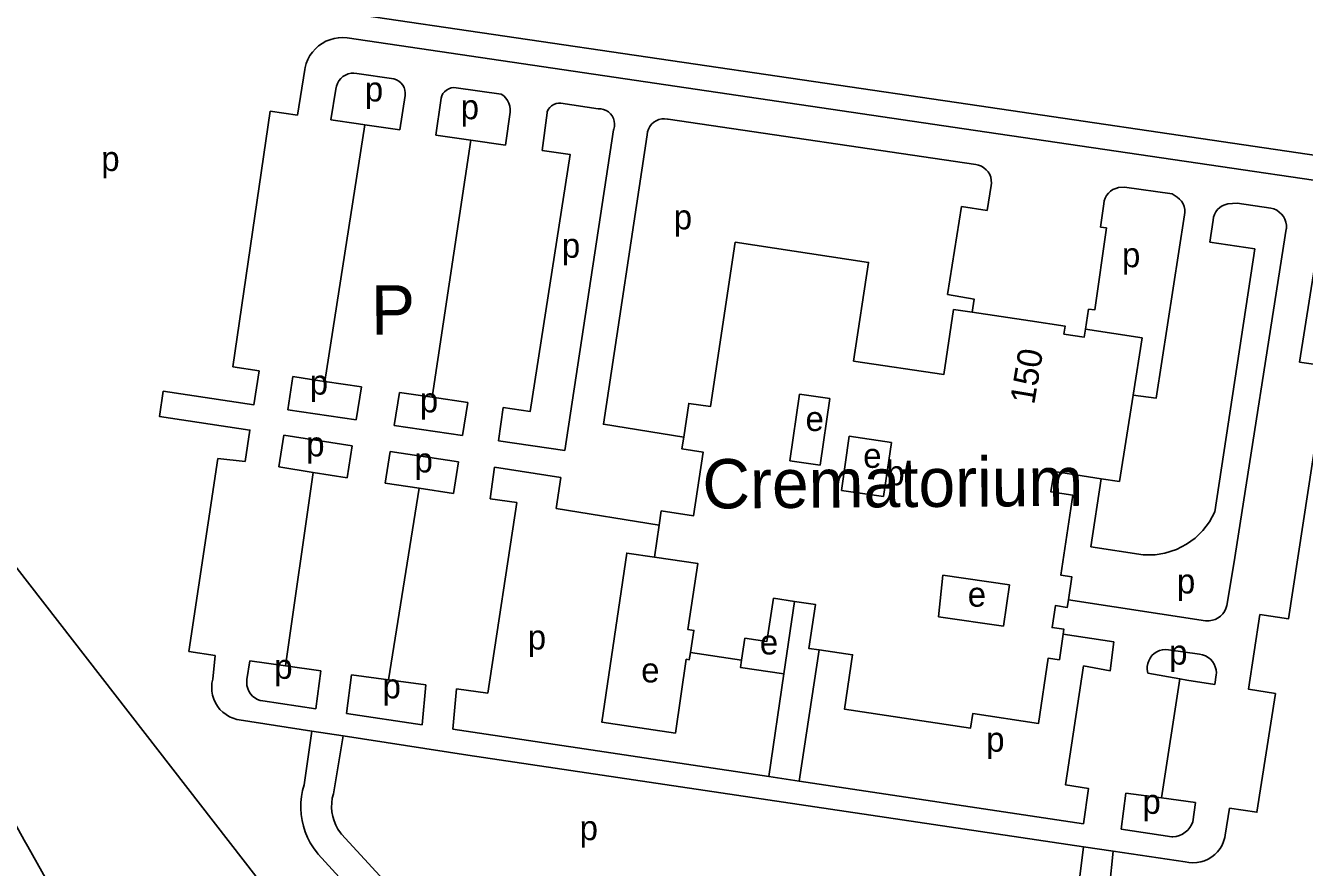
# Model space of a CAD drawing. Extents: x 156097 to 158136, y 385644 to 388348.
# Drawn here: x 156481.1 to 156688.7, y 385843.2 to 385979.8 of the extents above; entities that cross this region are included whole.
import ezdxf

# ---------------------------------------------------------------- set-up
doc = ezdxf.new("R2010")
doc.units = 0
for name, color, linetype in [('BLT_Basislijn', 7, 'Continuous'), ('BLT_Bebouwing', 7, 'Continuous'), ('BLT_Bebouwing_beschrifting', 7, 'Continuous'), ('BLT_Centroide', 7, 'Continuous'), ('BLT_Huisnummer', 7, 'Continuous')]:
    doc.layers.add(name, color=color, linetype=linetype)

msp = doc.modelspace()

# ---------------------------------------------------------------- linework, layer by layer
at = {"layer": 'BLT_Basislijn'}
for p, q in [((156526.39, 385972.7), (156525.24, 385965.31)), ((156534.87, 385972.08), (156540.88, 385971.22)), ((156531.46, 385969.52), (156530.63, 385964.53)), ((156550.97, 385969.74), (156558.3, 385968.71)), ((156542.7, 385968.51), (156541.83, 385962.92)), ((156548.51, 385967.67), (156547.65, 385962.08)), ((156567.99, 385967.23), (156574.03, 385966.35)), ((156520.79, 385965.95), (156514.73, 385924.48)), ((156520.79, 385965.95), (156525.24, 385965.31)), ((156530.63, 385964.53), (156535.15, 385963.89)), ((156559.74, 385965.8), (156559.01, 385960.45)), ((156565.73, 385965.7), (156564.96, 385959.59)), ((156585.38, 385964.65), (156635.31, 385957.31)), ((156536.14, 385963.74), (156529.68, 385922.09)), ((156535.15, 385963.89), (156536.14, 385963.74)), ((156536.14, 385963.74), (156541.83, 385962.92)), ((156576.51, 385962.92), (156568.64, 385910.87)), ((156553.34, 385961.26), (156547.07, 385919.53)), ((156547.65, 385962.08), (156553.34, 385961.26)), ((156553.34, 385961.26), (156559.01, 385960.45)), ((156637.83, 385953.89), (156637.15, 385949.85)), ((156659.48, 385953.63), (156667.2, 385952.52)), ((156637.15, 385949.85), (156633.02, 385950.46)), ((156656.12, 385950.92), (156655.58, 385947.14)), ((156683.24, 385950.23), (156677.73, 385951.02)), ((156656.54, 385947), (156655.58, 385947.14)), ((156685.73, 385946.79), (156677.19, 385892.5)), ((156653.11, 385930.57), (156653.63, 385933.85)), ((156519.02, 385923.79), (156514.73, 385924.48)), ((156524.47, 385922.91), (156523.64, 385917.49)), ((156528.84, 385922.21), (156524.47, 385922.91)), ((156529.68, 385922.09), (156528.84, 385922.21)), ((156535.59, 385921.22), (156529.68, 385922.09)), ((156535.59, 385921.22), (156534.76, 385915.85)), ((156541.76, 385920.31), (156540.91, 385914.95)), ((156547.07, 385919.53), (156541.76, 385920.31)), ((156552.87, 385918.68), (156547.07, 385919.53)), ((156523.64, 385917.49), (156534.76, 385915.85)), ((156552.87, 385918.68), (156552.01, 385913.32)), ((156558.6, 385917.84), (156557.83, 385912.46)), ((156540.91, 385914.95), (156552.01, 385913.32)), ((156523, 385913.36), (156522.21, 385908.21)), ((156523, 385913.36), (156534.11, 385911.67)), ((156534.11, 385911.67), (156533.3, 385906.46)), ((156540.25, 385910.74), (156539.44, 385905.56)), ((156540.25, 385910.74), (156551.33, 385909.06)), ((156557.83, 385912.46), (156568.64, 385910.87)), ((156512.28, 385909.57), (156507.6, 385878.24)), ((156512.28, 385909.57), (156516.71, 385909.08)), ((156551.33, 385909.06), (156550.52, 385903.93)), ((156522.21, 385908.21), (156527.76, 385907.34)), ((156523.26, 385875.96), (156527.76, 385907.34)), ((156527.76, 385907.34), (156533.3, 385906.46)), ((156557.21, 385908.16), (156556.49, 385903.06)), ((156557.21, 385908.16), (156567.98, 385906.53)), ((156539.44, 385905.56), (156544.98, 385904.75)), ((156544.98, 385904.75), (156540.02, 385873.67)), ((156544.98, 385904.75), (156550.52, 385903.93)), ((156677.19, 385892.5), (156676.07, 385885.71)), ((156605.91, 385886.39), (156604.18, 385874.63)), ((156672.61, 385883.26), (156650.35, 385886.64)), ((156657.74, 385879.86), (156649.52, 385881.08)), ((156507.6, 385878.24), (156511.84, 385877.61)), ((156511.46, 385873.75), (156511.84, 385877.61)), ((156609.9, 385878.55), (156606.68, 385857.22)), ((156671.65, 385877.81), (156666.61, 385878.55)), ((156517.02, 385873.7), (156517.48, 385876.77)), ((156523.26, 385875.96), (156517.48, 385876.77)), ((156529.03, 385875.15), (156523.26, 385875.96)), ((156528.2, 385868.97), (156529.03, 385875.15)), ((156533.15, 385868.23), (156533.99, 385874.48)), ((156540.02, 385873.67), (156533.99, 385874.48)), ((156546.05, 385872.86), (156540.02, 385873.67)), ((156604.18, 385874.63), (156601.73, 385857.96)), ((156663.25, 385874.75), (156668.47, 385873.82)), ((156668.47, 385873.82), (156665.46, 385854.51)), ((156668.47, 385873.82), (156669.61, 385873.62)), ((156669.61, 385873.62), (156674.15, 385872.91)), ((156674.37, 385874.49), (156674.15, 385872.91)), ((156545.46, 385866.39), (156546.05, 385872.86)), ((156550.41, 385865.65), (156551.01, 385872.19)), ((156556.13, 385871.51), (156551.01, 385872.19)), ((156519.57, 385870.26), (156528.2, 385868.97)), ((156515.73, 385867.18), (156527.57, 385865.35)), ((156533.15, 385868.23), (156545.46, 385866.39)), ((156526.28, 385856.64), (156527.57, 385865.35)), ((156527.57, 385865.35), (156532.62, 385864.57)), ((156550.41, 385865.65), (156601.73, 385857.96)), ((156531.05, 385855.16), (156532.62, 385864.57)), ((156601.73, 385857.96), (156606.68, 385857.22)), ((156606.68, 385857.22), (156652.81, 385850.32)), ((156671.01, 385853.78), (156665.46, 385854.51)), ((156670.57, 385850.65), (156671.01, 385853.78)), ((156675.81, 385848.48), (156676.53, 385852.86)), ((156548.36, 385831.24), (156532.39, 385848.62)), ((156658.9, 385849.41), (156667.15, 385848.17)), ((156652.07, 385840.48), (156652.83, 385846.59)), ((156652.83, 385846.59), (156657.63, 385845.88)), ((156528.59, 385845.37), (156544.95, 385827.58)), ((156657.05, 385840.01), (156657.63, 385845.88)), ((156657.63, 385845.88), (156669.29, 385844.14))]:
    msp.add_line(p, q, dxfattribs=at)
for points in [[(156533.84, 385981.8), (156634.01, 385967.07), (156733.92, 385952.37)], [(156533.26, 385977.84), (156532.55, 385977.89), (156531.85, 385977.86), (156531.16, 385977.74), (156530.48, 385977.55), (156529.83, 385977.29), (156529.22, 385976.95), (156528.64, 385976.54), (156528.12, 385976.08), (156527.65, 385975.55), (156527.25, 385974.98), (156526.91, 385974.36), (156526.65, 385973.71), (156526.46, 385973.03), (156526.39, 385972.7)], [(156533.26, 385977.84), (156633.43, 385963.11), (156733.61, 385948.37)], [(156534.87, 385972.08), (156534.39, 385972.13), (156533.92, 385972.1), (156533.45, 385972), (156533.01, 385971.82), (156532.6, 385971.57), (156532.24, 385971.25), (156531.94, 385970.88), (156531.71, 385970.46), (156531.55, 385970.01), (156531.46, 385969.52)], [(156540.88, 385971.22), (156541.3, 385971.06), (156541.68, 385970.84), (156542.02, 385970.54), (156542.3, 385970.2), (156542.52, 385969.8), (156542.66, 385969.38), (156542.72, 385968.94), (156542.7, 385968.51)], [(156550.97, 385969.74), (156550.56, 385969.77), (156550.15, 385969.72), (156549.76, 385969.59), (156549.41, 385969.39), (156549.1, 385969.12), (156548.84, 385968.8), (156548.66, 385968.43), (156548.54, 385968.04), (156548.51, 385967.67)], [(156558.3, 385968.71), (156558.7, 385968.42), (156559.05, 385968.08), (156559.33, 385967.68), (156559.55, 385967.24), (156559.69, 385966.77), (156559.76, 385966.29), (156559.74, 385965.8)], [(156567.99, 385967.23), (156567.59, 385967.24), (156567.19, 385967.18), (156566.81, 385967.03), (156566.46, 385966.82), (156566.17, 385966.54), (156565.93, 385966.21), (156565.77, 385965.83), (156565.73, 385965.7)], [(156574.03, 385966.35), (156574.48, 385966.34), (156574.92, 385966.24), (156575.33, 385966.08), (156575.71, 385965.84), (156576.04, 385965.53), (156576.31, 385965.18), (156576.51, 385964.78), (156576.64, 385964.35), (156576.69, 385963.9), (156576.66, 385963.46), (156576.55, 385963.02), (156576.51, 385962.92)], [(156581.96, 385962.14), (156582.03, 385962.6), (156582.18, 385963.05), (156582.4, 385963.46), (156582.7, 385963.83), (156583.05, 385964.15), (156583.44, 385964.41), (156583.88, 385964.59), (156584.34, 385964.69), (156584.81, 385964.72), (156585.28, 385964.67), (156585.38, 385964.65)], [(156581.96, 385962.14), (156574.87, 385915.14), (156587.91, 385913.04)], [(156432.92, 385958.38), (156438.13, 385950.17), (156442.61, 385939.52), (156555.51, 385794.04), (156558.57, 385794.04)], [(156564.96, 385959.59), (156569.47, 385958.94), (156562.97, 385917.19), (156558.6, 385917.84)], [(156635.31, 385957.31), (156635.78, 385957.21), (156636.23, 385957.03), (156636.65, 385956.78), (156637.02, 385956.46), (156637.33, 385956.09), (156637.58, 385955.67), (156637.75, 385955.22), (156637.85, 385954.74), (156637.87, 385954.26), (156637.83, 385953.89)], [(156656.12, 385950.92), (156656.19, 385951.39), (156656.34, 385951.84), (156656.56, 385952.27), (156656.85, 385952.65), (156657.2, 385952.97), (156657.6, 385953.24), (156658.04, 385953.43), (156658.5, 385953.55), (156659.48, 385953.63)], [(156667.2, 385952.52), (156668.04, 385952.02), (156668.41, 385951.7), (156668.72, 385951.33), (156668.97, 385950.91), (156669.14, 385950.46), (156669.24, 385949.98), (156669.26, 385949.5), (156669.22, 385949.13)], [(156633.02, 385950.46), (156630.75, 385936.23), (156635.06, 385935.45), (156634.75, 385933.33)], [(156673.84, 385948.26), (156673.91, 385948.74), (156674.06, 385949.19), (156674.28, 385949.61), (156674.57, 385949.99), (156674.92, 385950.32), (156675.32, 385950.58), (156675.76, 385950.78), (156676.22, 385950.9), (156677.73, 385951.02)], [(156683.24, 385950.23), (156683.72, 385950.09), (156684.18, 385949.88), (156684.59, 385949.59), (156684.95, 385949.25), (156685.26, 385948.85), (156685.49, 385948.41), (156685.65, 385947.93), (156685.74, 385947.44), (156685.74, 385946.94), (156685.73, 385946.79)], [(156673.84, 385948.26), (156673.34, 385944.7), (156680.61, 385943.6), (156674.11, 385900.94), (156673.25, 385899.32), (156672.17, 385897.88), (156670.94, 385896.67), (156669.55, 385895.66), (156667.93, 385894.83), (156666.02, 385894.22), (156664.43, 385893.98), (156662.48, 385893.98), (156654.01, 385895.27), (156655.67, 385906.31)], [(156669.22, 385949.13), (156664.61, 385919.39), (156660.87, 385919.89)], [(156653.63, 385933.85), (156654.64, 385933.7), (156656.54, 385947)], [(156691.18, 385946.05), (156687.9, 385925.24), (156692.35, 385924.56), (156686.07, 385883.56), (156681.44, 385884.26), (156679.62, 385872.15), (156683.97, 385871.44)], [(156516.71, 385909.08), (156517.51, 385914.19), (156502.81, 385916.42), (156503.44, 385920.51), (156518.13, 385918.29), (156519.02, 385923.79)], [(156484.47, 385841.19), (156481.43, 385846.61), (156480.84, 385847.67), (156478.15, 385852.55), (156475.47, 385857.49), (156472.53, 385862.96), (156469.64, 385868.44), (156466.77, 385873.94), (156463.94, 385879.47), (156461.15, 385885.01), (156458.39, 385890.56), (156455.66, 385896.14), (156452.97, 385901.73), (156450.31, 385907.34), (156447.69, 385912.96), (156445.15, 385918.63)], [(156567.98, 385906.53), (156567.22, 385901.48), (156583.94, 385898.75)], [(156556.49, 385903.06), (156560.81, 385902.43), (156556.13, 385871.51)], [(156583.17, 385893.6), (156578.68, 385894.24), (156574.62, 385866.8), (156586.56, 385865.03), (156588.33, 385877), (156588.81, 385876.93), (156589, 385878.13)], [(156676.07, 385885.71), (156675.93, 385885.23), (156675.7, 385884.78), (156675.41, 385884.37), (156675.06, 385884.01), (156674.65, 385883.71), (156674.21, 385883.48), (156673.73, 385883.33), (156673.23, 385883.25), (156672.73, 385883.25), (156672.61, 385883.26)], [(156657.74, 385879.86), (156657.15, 385875.15), (156652.82, 385875.93), (156649.87, 385856.64), (156653.61, 385856.05), (156652.81, 385850.32)], [(156666.61, 385878.55), (156666.11, 385878.59), (156665.62, 385878.54), (156665.15, 385878.41), (156664.7, 385878.2), (156664.29, 385877.93), (156663.93, 385877.6), (156663.63, 385877.21), (156663.4, 385876.77), (156663.24, 385876.31), (156663.15, 385875.82), (156663.15, 385875.33), (156663.25, 385874.75)], [(156671.65, 385877.81), (156672.13, 385877.72), (156672.6, 385877.55), (156673.03, 385877.31), (156673.41, 385877.01), (156673.74, 385876.64), (156674.01, 385876.23), (156674.21, 385875.78), (156674.34, 385875.3), (156674.38, 385874.8), (156674.37, 385874.49)], [(156597.32, 385876.86), (156597.13, 385875.68), (156604.18, 385874.63)], [(156511.46, 385873.75), (156511.34, 385873.11), (156511.29, 385872.46), (156511.33, 385871.81), (156511.44, 385871.16), (156511.63, 385870.54), (156511.9, 385869.95), (156512.24, 385869.39), (156512.64, 385868.88), (156513.1, 385868.42), (156513.62, 385868.02), (156514.18, 385867.69), (156514.78, 385867.43), (156515.4, 385867.24), (156515.73, 385867.18)], [(156517.02, 385873.7), (156516.98, 385873.21), (156517.02, 385872.73), (156517.14, 385872.26), (156517.33, 385871.81), (156517.59, 385871.4), (156517.92, 385871.04), (156518.3, 385870.74), (156518.72, 385870.5), (156519.18, 385870.34), (156519.57, 385870.26)], [(156676.53, 385852.86), (156680.97, 385852.19), (156683.97, 385871.44)], [(156532.62, 385864.57), (156552.86, 385861.45), (156652.83, 385846.59)], [(156526.28, 385856.64), (156526.03, 385855.7), (156525.86, 385854.74), (156525.76, 385853.77), (156525.75, 385852.79), (156525.81, 385851.82), (156525.96, 385850.86), (156526.18, 385849.91), (156526.48, 385848.98), (156526.86, 385848.08), (156527.3, 385847.21), (156527.82, 385846.38), (156528.4, 385845.6), (156528.59, 385845.37)], [(156531.05, 385855.16), (156530.87, 385854.44), (156530.77, 385853.7), (156530.74, 385852.96), (156530.8, 385852.22), (156530.93, 385851.49), (156531.15, 385850.77), (156531.43, 385850.09), (156531.79, 385849.44), (156532.22, 385848.83), (156532.39, 385848.62)], [(156665.46, 385854.51), (156659.71, 385855.26), (156658.9, 385849.41)], [(156670.57, 385850.65), (156670.36, 385850.16), (156670.08, 385849.7), (156669.73, 385849.28), (156669.33, 385848.92), (156668.88, 385848.63), (156668.38, 385848.4), (156667.87, 385848.25), (156667.33, 385848.18), (156667.15, 385848.17)], [(156669.29, 385844.14), (156669.93, 385844.02), (156670.57, 385843.97), (156671.22, 385844.01), (156671.86, 385844.12), (156672.48, 385844.31), (156673.07, 385844.58), (156673.62, 385844.92), (156674.12, 385845.32), (156674.58, 385845.78), (156674.97, 385846.29), (156675.3, 385846.85), (156675.55, 385847.45), (156675.73, 385848.07), (156675.81, 385848.48)]]:
    msp.add_lwpolyline(points, dxfattribs=at)
at = {"layer": 'BLT_Bebouwing'}
for p, q in [((156662.31, 385929.16), (156660.87, 385919.89)), ((156606.71, 385920.04), (156605.14, 385909.21)), ((156611.61, 385919.33), (156606.71, 385920.04)), ((156610.05, 385908.5), (156611.61, 385919.33)), ((156660.87, 385919.89), (156658.68, 385905.85)), ((156613.52, 385904.39), (156614.79, 385913.19)), ((156614.79, 385913.19), (156621.62, 385912.2)), ((156621.62, 385912.2), (156620.34, 385903.4)), ((156605.14, 385909.21), (156610.05, 385908.5)), ((156658.68, 385905.85), (156655.67, 385906.31)), ((156620.34, 385903.4), (156613.52, 385904.39)), ((156583.17, 385893.6), (156583.94, 385898.75)), ((156629.99, 385890.66), (156629.25, 385883.87)), ((156629.99, 385890.66), (156640.78, 385889.1)), ((156640.78, 385889.1), (156639.81, 385882.38)), ((156629.25, 385883.87), (156639.81, 385882.38)), ((156597.32, 385876.86), (156589, 385878.13))]:
    msp.add_line(p, q, dxfattribs=at)
for points in [[(156587.91, 385913.04), (156588.74, 385918.54), (156592.25, 385918.01), (156596.27, 385944.68), (156617.92, 385941.41), (156615.5, 385925.41), (156630.12, 385923.21), (156631.71, 385933.78)], [(156631.71, 385933.78), (156634.75, 385933.33)], [(156634.75, 385933.33), (156644.15, 385931.95)], [(156644.15, 385931.95), (156649.83, 385931.07), (156649.64, 385929.79), (156652.92, 385929.29), (156653.11, 385930.57)], [(156653.11, 385930.57), (156662.31, 385929.16)], [(156587.91, 385913.04), (156587.62, 385911.13), (156591.08, 385910.61), (156589.51, 385900.29), (156584.27, 385901.07), (156583.94, 385898.75)], [(156655.67, 385906.31), (156651.59, 385906.92), (156648.03, 385907.47), (156647.53, 385904.17), (156651.09, 385903.62)], [(156651.09, 385903.62), (156649.94, 385896.08), (156649.12, 385890.67), (156650.91, 385890.41), (156650.35, 385886.64)], [(156589, 385878.13), (156589.57, 385881.7), (156588.61, 385881.83), (156590.22, 385892.54), (156583.17, 385893.6)], [(156597.32, 385876.86), (156597.86, 385880.43), (156601.42, 385879.89), (156602.49, 385886.91), (156605.91, 385886.39)], [(156605.91, 385886.39), (156609.31, 385885.87), (156608.23, 385878.75), (156609.9, 385878.55)], [(156650.35, 385886.64), (156650.17, 385885.43), (156648.24, 385885.72), (156647.71, 385882.16), (156649.64, 385881.87), (156649.52, 385881.08)], [(156649.52, 385881.08), (156648.9, 385876.92), (156647.1, 385877.2), (156645.51, 385866.59), (156634.83, 385868.2), (156634.47, 385865.83), (156614.01, 385868.91), (156615.34, 385877.73), (156609.9, 385878.55)]]:
    msp.add_lwpolyline(points, dxfattribs=at)

# ---------------------------------------------------------------- texts
at = {"layer": 'BLT_Bebouwing_beschrifting'}
for s, height, p in [('P', 8, (156537.19, 385929.67)), ('Crematorium', 7.9999, (156590.98, 385901.46))]:
    msp.add_text(s, height=height, rotation=0.4199, dxfattribs=at).set_placement(p)
at = {"layer": 'BLT_Centroide'}
for s, p in [('p', (156536.15, 385967.53)), ('p', (156551.71, 385964.65)), ('p', (156493.37, 385956.25)), ('p', (156586.3, 385946.78)), ('p', (156568.14, 385942.16)), ('p', (156659.06, 385940.63)), ('p', (156527.21, 385919.96)), ('p', (156545.08, 385917.08)), ('e', (156607.69, 385914.05)), ('p', (156526.64, 385909.93)), ('p', (156544.22, 385907.33)), ('e', (156617.05, 385908.07)), ('b', (156620.8, 385905.25)), ('p', (156667.98, 385887.68)), ('e', (156634.02, 385885.54)), ('p', (156562.6, 385878.59)), ('e', (156600.27, 385877.78)), ('p', (156666.71, 385876.14)), ('p', (156521.45, 385873.83)), ('e', (156581.01, 385873.25)), ('p', (156539.03, 385870.66)), ('p', (156637.02, 385862.01)), ('p', (156662.38, 385851.92)), ('p', (156571.02, 385847.65))]:
    msp.add_text(s, height=4, dxfattribs=at).set_placement(p)
at = {"layer": 'BLT_Huisnummer'}
msp.add_text('150', height=4, rotation=80.4209, dxfattribs=at).set_placement((156644.8, 385918.23))

doc.saveas('drawing.dxf')
